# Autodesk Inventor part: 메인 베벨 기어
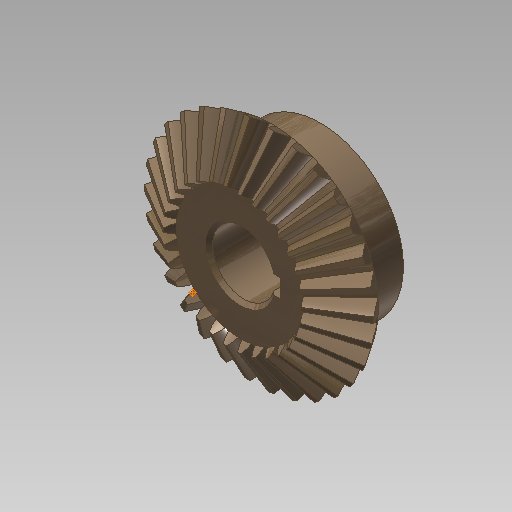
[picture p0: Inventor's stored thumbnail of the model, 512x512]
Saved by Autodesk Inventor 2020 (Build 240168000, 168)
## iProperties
CustomPartVersion: 1
Created: 2016-04
Part Number: 메인 베벨 기어
Material: 강철, 탄소
Document SubType Name: Modeling
Designer: mdu
Categories: <?xml version="1.0" encoding="UTF-16"?> <MemberInstance><Categories><FamilyTemplate><FamilyTemplateParameter ValueType="xs:double" Id="1" ObjectReferenceKey="da
Mass: 269.926 g
Surface Area: 108.837 cm^2
Volume: 34.2981 cm^3
Density: 7.87 g/cm^3
Appearance: 얼룩무늬
Author: mdu
Revision Number: 1
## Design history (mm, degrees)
node "맨 위 점"
node "메쉬 평면2"
sketch "톱니 본체 스케치"
  geometry: L1 (0, 0)-(28.669, -21.997); L2 (28.669, -21.997)-(31.109, -18.336); L3 (31.109, -18.336)-(0, 0); L4 (30, -20)-(0, 0); L5 (17.219, -13.212)-(18.685, -11.013); L6 (28.669, -21.997)-(17.219, -13.212); L7 (31.109, -18.336)-(18.685, -11.013); L8 (0, -39.387)-(0, 6.564) reference; L9 (0, -20)-(31.109, -20)
  constraints: 16 end point, 4 point on line, 3 perpendicular, 2 collinear, 1 horizontal alignment, 1 vertical alignment
  dimensions: "d0" = 60 diameter of L4.start L8 (= da_de); "d1" = 57.33744 diameter of L1.end L8 (= da_dfe); "d2" = 62.2188 diameter of L2.end L8 (= da_dae); "d3" = 14.4 distance between parallel lines of L2 L5 (= da_b); "d4" = 18.3359 vertical distance of L2.end L1.start (= da_ve)
revolve "톱니 본체" sketch "톱니 본체 스케치" stored, may be unused: angle "d5" = 90 deg
node "시작점"
node "톱니 평면"
sketch "시작 스케치"
  geometry: L1 (0, -23.505)-(0, 10.645) reference; L2 (-0.709, -2.928)-(0.709, -2.928); A1 r 19.188 centre (-19.457, -7.014) between (-0.709, -2.928) and (-3.232, 3.229); A2 r 19.188 centre (19.457, -7.014) between (3.232, 3.229) and (0.709, -2.928); A3 r 57.403 centre (0, -54.083) between (3.232, 3.229) and (-3.232, 3.229); 1 further point
  constraints: 6 point on circle, 3 centre point, 3 symmetric about line, 2 end point, 1 coincident, 1 perpendicular, 1 other
  dimensions: "d7" = 19.18795 radius of A1 (= fd_rr); "d8" = 19.45712 horizontal distance of point (0, -54.083) A1.centre (= fd_x); "d9" = 47.06905 vertical distance of point (0, -54.083) A1.centre (= fd_y); "d57" = 57.40327 radius of A3 (= 0.5 x fd_dva + 0.3 x da_he); "d58" = 51.15527 distance from line of A3.centre L2 (= 0.5 x fd_dva - 1.12 x da_he)
node "끝점"
  node "끝 평면"
sketch "3D 스케치 오른쪽"
  node "Helical Curve Right" dims "d65" = 229.90621 (computed from da_dm, da_delta, da_beta), "d66" = 31.5, "d67" = 60 (= da_de), "d68" = -9.82794 (= -da_delta), "d69" = 8.10972 (computed from fd_loft, da_delta)
node "끝 평면 오른쪽"
sketch "끝 스케치 오른쪽"
  geometry: L1 (0, -41.54)-(0, 13.178) reference; L2 (-0.422, -1.69)-(0.422, -1.69); A1 r 11.427 centre (-11.587, -4.123) between (-0.422, -1.69) and (-1.925, 1.977); A2 r 11.427 centre (11.587, -4.123) between (1.925, 1.977) and (0.422, -1.69); A3 r 34.184 centre (0, -32.153) between (1.925, 1.977) and (-1.925, 1.977); 1 further point
  constraints: 6 point on circle, 3 centre point, 3 symmetric about line, 2 end point, 1 coincident, 1 perpendicular, 1 other
  dimensions: "d70" = 11.58699 horizontal distance of A3.centre A1.centre (computed from fd_x, fd_ratio); "d71" = 28.03028 vertical distance of point (0, -32.153) A1.centre (computed from fd_y, fd_ratio); "d72" = 11.4267 radius of A1 (computed from fd_rr, fd_ratio); "d73" = 30.46369 distance from line of point (0, -32.153) L2 (computed from d58, fd_ratio); "d74" = 34.18446 radius of A3 (computed from d57, fd_ratio)
feature "로프트 오른쪽" sketch "끝 스케치 오른쪽" dims "d75" = 0, "d77" = 0, "d79" = 0, "d80" = 90 deg, "d85" = 20, "d92" = 90 deg, "d93" = 90 deg, "da_teethtype" = 0 [user parameter]
sketch "3D 스케치 왼쪽"
  node "Helical Curve Left" dims "d26" = 229.90621 (computed from da_dm, da_delta, da_beta), "d27" = 8.10972 (computed from fd_loft, da_delta), "d28" = 60 (= da_de), "d29" = -9.82794 (= -da_delta)
node "끝 평면 왼쪽"
sketch "끝 스케치 왼쪽" dims "d56" = 10.3728 (derived)
  geometry: L1 (0, -43.753)-(0, 15.405) reference; L2 (-0.422, -1.678)-(0.422, -1.678); A1 r 11.427 centre (-11.587, -4.111) between (-0.422, -1.678) and (-1.925, 1.988); A2 r 11.427 centre (11.587, -4.111) between (1.925, 1.988) and (0.422, -1.678); A3 r 34.184 centre (0, -32.142) between (1.925, 1.988) and (-1.925, 1.988); 2 further points; 1 other entity
  constraints: 6 point on circle, 3 centre point, 3 symmetric about line, 2 end point, 1 coincident, 2 other
  dimensions: "d30" = 11.4267 radius of A1 (computed from fd_rr, fd_ratio); "d31" = 11.58699 horizontal distance of point (0, -32.142) A1.centre (computed from fd_x, fd_ratio); "d32" = 28.03028 vertical distance of A1.centre point (0, -32.142) (computed from fd_y, fd_ratio); "d61" = 34.18446 radius of A3 (computed from d57, fd_ratio); "d62" = 30.46369 distance from line of point (0, -32.142) L2 (computed from d58, fd_ratio)
feature "로프트 왼쪽" sketch "끝 스케치 왼쪽" dims "d35" = 0, "d37" = 0, "d39" = 0, "d40" = 90 deg, "d84" = 10, "d90" = 90 deg, "d91" = 90 deg, "da_teethtype" = 0 [user parameter]
sketch "본체 스케치"
  geometry: L1 (0, -35.038)-(0, -19.531) reference; L2 (28.669, -21.997)-(17.219, -13.212) reference; L3 (17.219, -13.212)-(0, -13.212); L4 (28.669, -21.997)-(0, -21.997)
  constraints: 4 end point, 2 perpendicular, 2 point on line
revolve "본체 고정" sketch "본체 스케치" stored, may be unused: angle "d46" = 90 deg
feature "피치 지름" dims angle "d47" = 90 deg
sketch "스케치8"
  geometry: C1 r 22.5 at (0, 0); 1 further point
  constraints: 1 centre point, 1 coincident
  dimensions: "d94" = 45 diameter of C1
extrude "돌출1" join sketch "스케치8" distance "d95" = 13; taper "d96" = 0 deg
sketch "스케치9"
  geometry: 1 further point
hole "구멍1" sketch "스케치9" at (0, 0) diameter "d97" = 17; stored, may be unused: countersink angle "d101" = 90 deg, drill point angle "d103" = 118 deg; dims "d98" = 6, "d99" = 4, "d100" = 2, "d102" = 8
sketch "스케치10"
  geometry: L1 (8.124, 2.5)-(10.8, 2.5); L2 (10.8, 2.5)-(10.8, -2.5); L3 (10.8, -2.5)-(8.124, -2.5); A1 r 8.5 centre (0, 0) between (8.124, 2.5) and (8.124, -2.5) reference; 1 further point
  constraints: 6 end point, 2 parallel, 2 point on circle, 1 horizontal, 1 perpendicular
  dimensions: "d104" = 5 distance of L1.end L2.end; "d112" = 19.3 dimension on A1 L2
extrude "돌출2" cut sketch "스케치10" extent not by distance; stored distance "d106" = 10; taper "d107" = 0 deg
chamfer "모따기1" distance "d108" = 1; stored, may be unused: second distance "d109" = 2, angle "d110" = 45 deg
fillet "모깎기1" dims "d111" = 2
body "Solid1"
feature "로프트" dims "d17" = 0, "d18" = 90 deg, "d19" = 0, "d20" = 90 deg, "d89" = 0, "da_teethtype" = 0 [user parameter]
pattern_circular "원형 패턴" dims angle "d22" = 360 deg, "d88" = 0, "da_teethtype" = 0 [user parameter]
pattern_circular "원형 패턴 오른쪽" dims angle "d82" = 360 deg, "da_teethtype" = 0 [user parameter]
pattern_circular "원형 패턴 왼쪽" dims angle "d42" = 360 deg, "da_teethtype" = 0 [user parameter]
sketch "끝 스케치"
  geometry: L1 (0, -15.359)-(0, 6.983) reference; L2 (-0.422, -1.69)-(0.422, -1.69); A1 r 11.427 centre (-11.587, -4.123) between (-0.422, -1.69) and (-1.925, 1.977); A2 r 11.427 centre (11.587, -4.123) between (1.925, 1.977) and (0.422, -1.69); A3 r 34.184 centre (0, -32.153) between (1.925, 1.977) and (-1.925, 1.977); 1 further point
  constraints: 6 point on circle, 3 centre point, 3 symmetric about line, 2 end point, 1 coincident, 1 other
  dimensions: "d12" = 11.4267 radius of A1 (computed from fd_rr, fd_ratio); "d15" = 11.58699 horizontal distance of A1.centre point (0, -32.153) (computed from fd_x, fd_ratio); "d16" = 28.03028 vertical distance of A1.centre point (0, -32.153) (computed from fd_y, fd_ratio); "d59" = 34.18446 radius of A3 (computed from d57, fd_ratio); "d60" = 30.46369 distance from line of A3.centre L2 (computed from d58, fd_ratio)
sketch "Sketch6"
  geometry: L1 (30, -20)-(0, 0) reference; L2 (0, -37.8)-(0, 6.3) reference
body "Srf1"
other parameters: "da_b" = 14.4 [user parameter; used in 2 equation terms], "da_de" = 60 [user parameter; used in 4 equation terms], "da_dae" = 62.2188 [user parameter; used in 2 equation terms], "da_dfe" = 57.33744 [user parameter; used in 1 equation term], "da_le" = 36.05551 [user parameter; used in 1 equation term], "da_omega" = 90 deg [user parameter; used in 1 equation term], "da_beta" = 0 [user parameter; used in 2 equation terms], "da_delta" = 9.82794 [user parameter; used in 8 equation terms], "da_alpha" = 20 deg [user parameter; used in 2 equation terms], "da_he" = 4.4 [user parameter; used in 4 equation terms], "da_ve" = 18.3359 [user parameter; used in 1 equation term], "fd_dv" = 108.16654 (computed from da_de, da_delta) [user parameter; used in 1 equation term], "fd_dva" = 112.16654 (computed from da_dae, da_delta) [user parameter; used in 3 equation terms], "fd_dvb" = 101.6433 (computed from fd_dv, da_alpha) [user parameter; used in 2 equation terms], "da_zv" = 540.83269 [user parameter; used in 1 equation term], "fd_loft" = 14.62 (= da_b + 0.05 x da_he) [user parameter; used in 4 equation terms], "fd_ratio" = 5.95514 (computed from da_le, fd_loft) [user parameter; used in 15 equation terms], "fd_rr" = 19.18795 (computed from fd_dd, fd_dvb) [user parameter; used in 6 equation terms], "fd_angle" = 0.29367 (computed from da_zv) [user parameter; used in 4 equation terms], "fd_x1" = 1.58802 (computed from da_dvw, fd_angle) [user parameter; used in 1 equation term], "fd_y1" = 54.05995 (computed from da_dvw, fd_angle) [user parameter; used in 1 equation term], "fd_x2" = 17.8691 (computed from fd_rr, fd_angle2, fd_angle) [user parameter; used in 1 equation term], "fd_y2" = 6.9909 (computed from fd_rr, fd_angle2, fd_angle) [user parameter; used in 1 equation term], "fd_x" = 19.45712 (= fd_x1 + fd_x2) [user parameter; used in 4 equation terms], "fd_y" = 47.06905 (= fd_y1 - fd_y2) [user parameter; used in 4 equation terms], "fd_angle2" = 3.43555 (computed from fd_dvb, fd_dd, da_alpha) [user parameter; used in 2 equation terms], "fd_dd" = 108.64654 (= fd_dva - 0.8 x da_he) [user parameter; used in 2 equation terms], "da_dvw" = 108.16654 [user parameter; used in 2 equation terms], "d11" = 14.62 (= fd_loft), "da_dm" = 48.01848 [user parameter; used in 2 equation terms], "da_x" = 0 [user parameter], "da_m" = 2 [user parameter], "d48" = 0, "d49" = 0, "d50" = 90 deg (= da_omega), "d51" = 6 deg (computed from da_z), "d52" = 0, "d53" = 0, "d54" = 0
